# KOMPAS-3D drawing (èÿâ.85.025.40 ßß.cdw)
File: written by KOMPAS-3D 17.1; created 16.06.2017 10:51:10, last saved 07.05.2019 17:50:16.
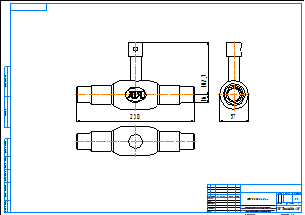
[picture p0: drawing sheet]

Sheet 1: A2, landscape

Title block, sheet 1: name: КШГ.85.025.40 сс; material: Внимание! Данный продукт является объектом авторского права ООО «Торговый Дом АДЛ». / Запрещается изменение, копирование, распространение / (в том числе путем копирования на другие сайты и ресурсы в Интернете) / или любое иное использование информации и объектов без предварительного / согласия правообладателя (ООО «Торговый Дом АДЛ»).; scale: 1:1; sheets: 1; organisation: ООО "Торговый дом АДЛ"; sheet format: A2; stored path: C:\Users\tra\Desktop\2д чертежи\Шаровые краны БИВАЛ\КШ_Бивал_серия_82_85\KOMPAS 2D\КШГ.85.025.40 сс.cdw

Views: Спереди 1, Проекционный вид 2, Проекционный вид 3
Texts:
  Klimkovich
  ADL
Dimensions and other numbers on the sheet: 230; 102,7; 16; 57; 1:1; 1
